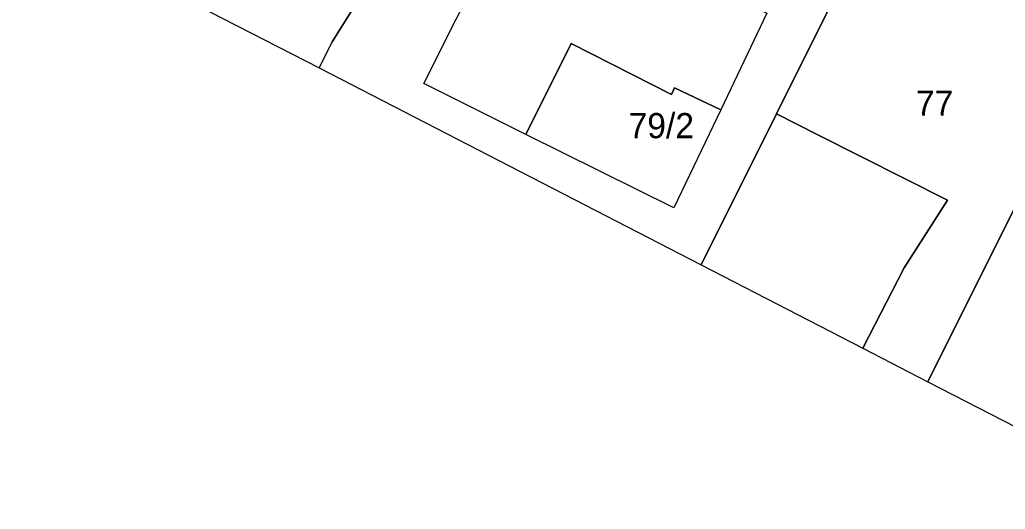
# Model space of a CAD drawing. Extents: x -559654 to -559448, y -1076607 to -1076478.
# Drawn here: x -559569.9 to -559511.1, y -1076594.5 to -1076565.3 of the extents above; entities that cross this region are included whole.
import ezdxf

# ---------------------------------------------------------------- set-up
doc = ezdxf.new("R2010")
doc.units = 0
doc.layers.add('Parcela-polygon', color=7, linetype='Continuous')
doc.layers.add('Parcela-text', color=7, linetype='Continuous')

msp = doc.modelspace()

# ---------------------------------------------------------------- linework, layer by layer
at = {"layer": 'Parcela-polygon'}
for p, q in [((-559569.856, -1076558.926), (-559551.999, -1076568.129)), ((-559551.999, -1076568.129), (-559529.198, -1076579.881)), ((-559529.198, -1076579.881), (-559519.553, -1076584.851)), ((-559519.553, -1076584.851), (-559515.683, -1076586.846)), ((-559515.683, -1076586.846), (-559500.912, -1076594.458))]:
    msp.add_line(p, q, dxfattribs=at)
for points in [[(-559551.999, -1076568.129), (-559551.22, -1076566.57), (-559550.05, -1076564.71), (-559551.63, -1076563.88), (-559549.91, -1076560.67), (-559552.84, -1076557), (-559560.94, -1076553.02), (-559556.49, -1076543.97), (-559548.32, -1076548.02), (-559546.54, -1076544.48), (-559559.21, -1076537.91), (-559569.856, -1076558.926)], [(-559529.198, -1076579.881), (-559524.71, -1076570.87), (-559518.69, -1076558.79), (-559538.34, -1076548.73), (-559542.4, -1076556.72), (-559545.15, -1076562.4), (-559547.78, -1076561.13), (-559550.05, -1076564.71), (-559551.22, -1076566.57), (-559551.999, -1076568.129)], [(-559539.65, -1076572.09), (-559545.74, -1076569.06), (-559539.94, -1076557.48), (-559534.35, -1076560.25), (-559532.8, -1076557.23), (-559527.46, -1076559.95), (-559529.02, -1076563.03), (-559525.28, -1076564.87), (-559528.02, -1076570.62), (-559530.82, -1076576.47), (-559539.65, -1076572.09)], [(-559515.683, -1076586.846), (-559505.11, -1076565.7), (-559518.69, -1076558.79), (-559524.71, -1076570.87), (-559522.23, -1076572.11), (-559514.5, -1076576.01), (-559517.09, -1076580.05), (-559519.553, -1076584.851)], [(-559500.912, -1076594.458), (-559489.07, -1076574.14), (-559505.11, -1076565.7), (-559515.683, -1076586.846)], [(-559519.553, -1076584.851), (-559517.09, -1076580.05), (-559514.5, -1076576.01), (-559522.23, -1076572.11), (-559524.71, -1076570.87), (-559529.198, -1076579.881)]]:
    msp.add_lwpolyline(points, dxfattribs=at)
for points in [[(-559545.74, -1076569.06), (-559539.94, -1076557.48), (-559534.35, -1076560.25), (-559532.8, -1076557.23), (-559527.46, -1076559.95), (-559529.02, -1076563.03), (-559525.28, -1076564.87), (-559528.02, -1076570.62), (-559530.78, -1076569.31), (-559530.97, -1076569.71), (-559536.96, -1076566.67), (-559539.65, -1076572.09)], [(-559530.97, -1076569.71), (-559530.78, -1076569.31), (-559528.02, -1076570.62), (-559530.82, -1076576.47), (-559539.65, -1076572.09), (-559536.96, -1076566.67)]]:
    msp.add_lwpolyline(points, close=True, dxfattribs=at)

# ---------------------------------------------------------------- texts
at = {"layer": 'Parcela-text'}
for s, p in [('77', (-559516.39, -1076570.98)), ('79/2', (-559533.53, -1076572.32))]:
    msp.add_text(s, height=1.5, dxfattribs=at).set_placement(p)

doc.saveas('drawing.dxf')
